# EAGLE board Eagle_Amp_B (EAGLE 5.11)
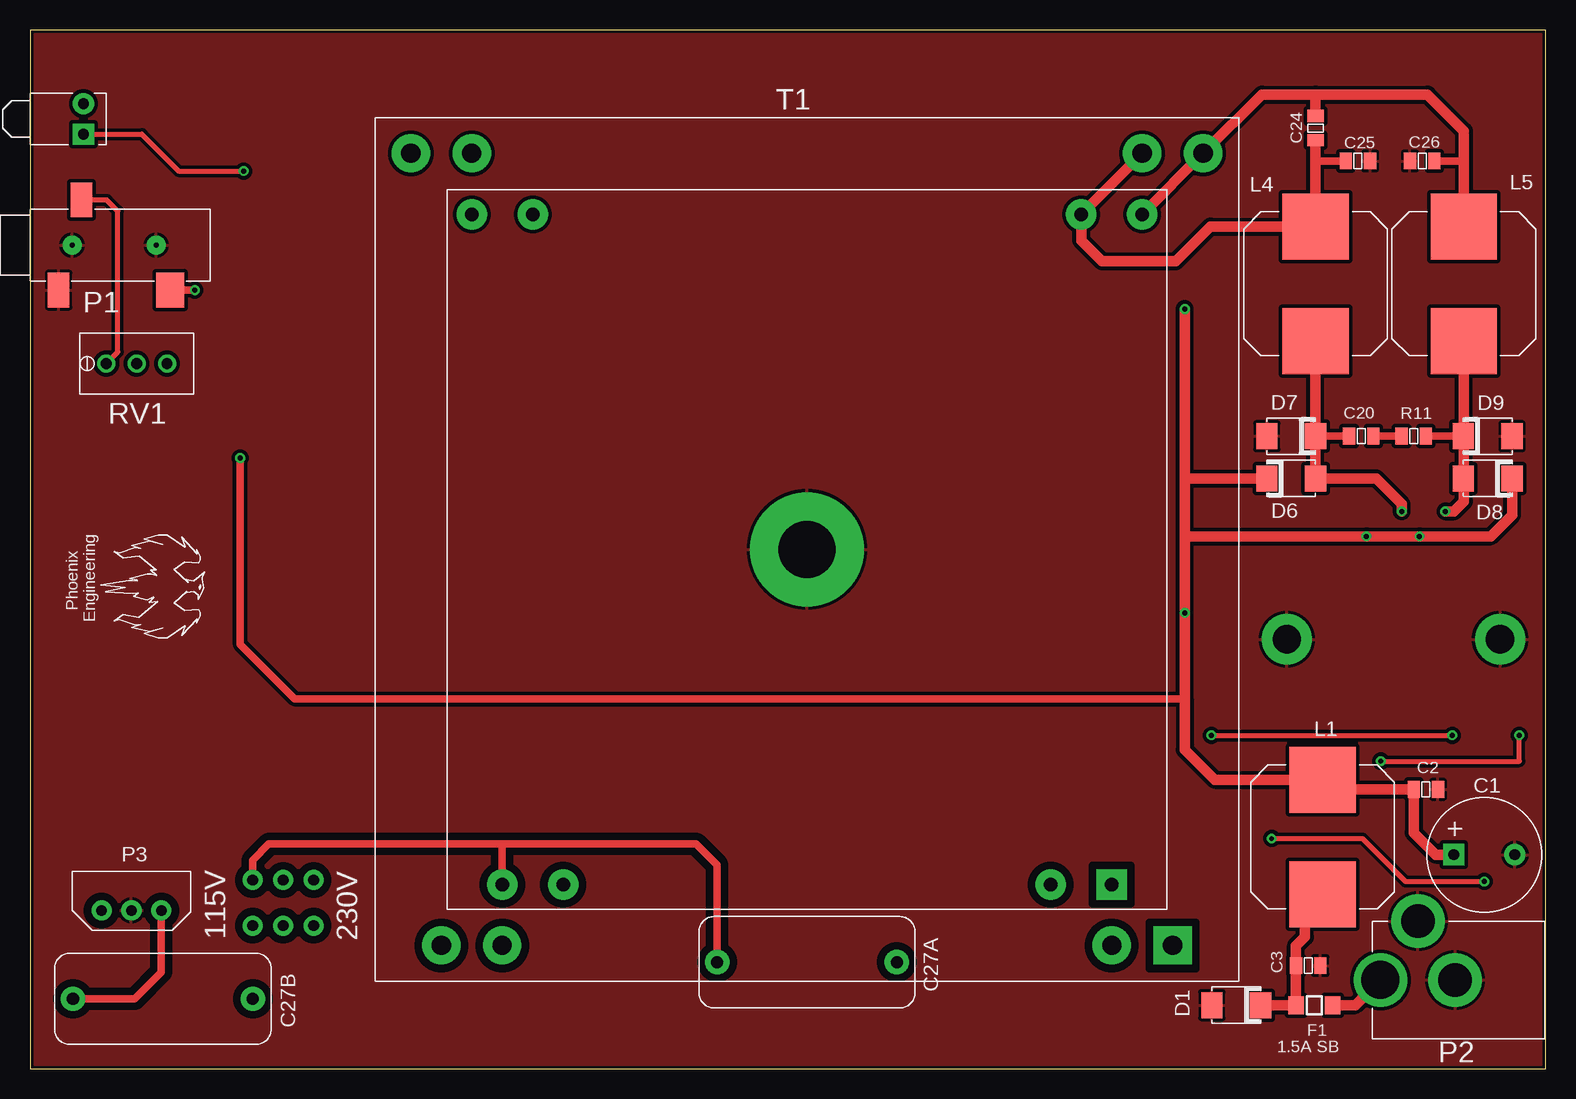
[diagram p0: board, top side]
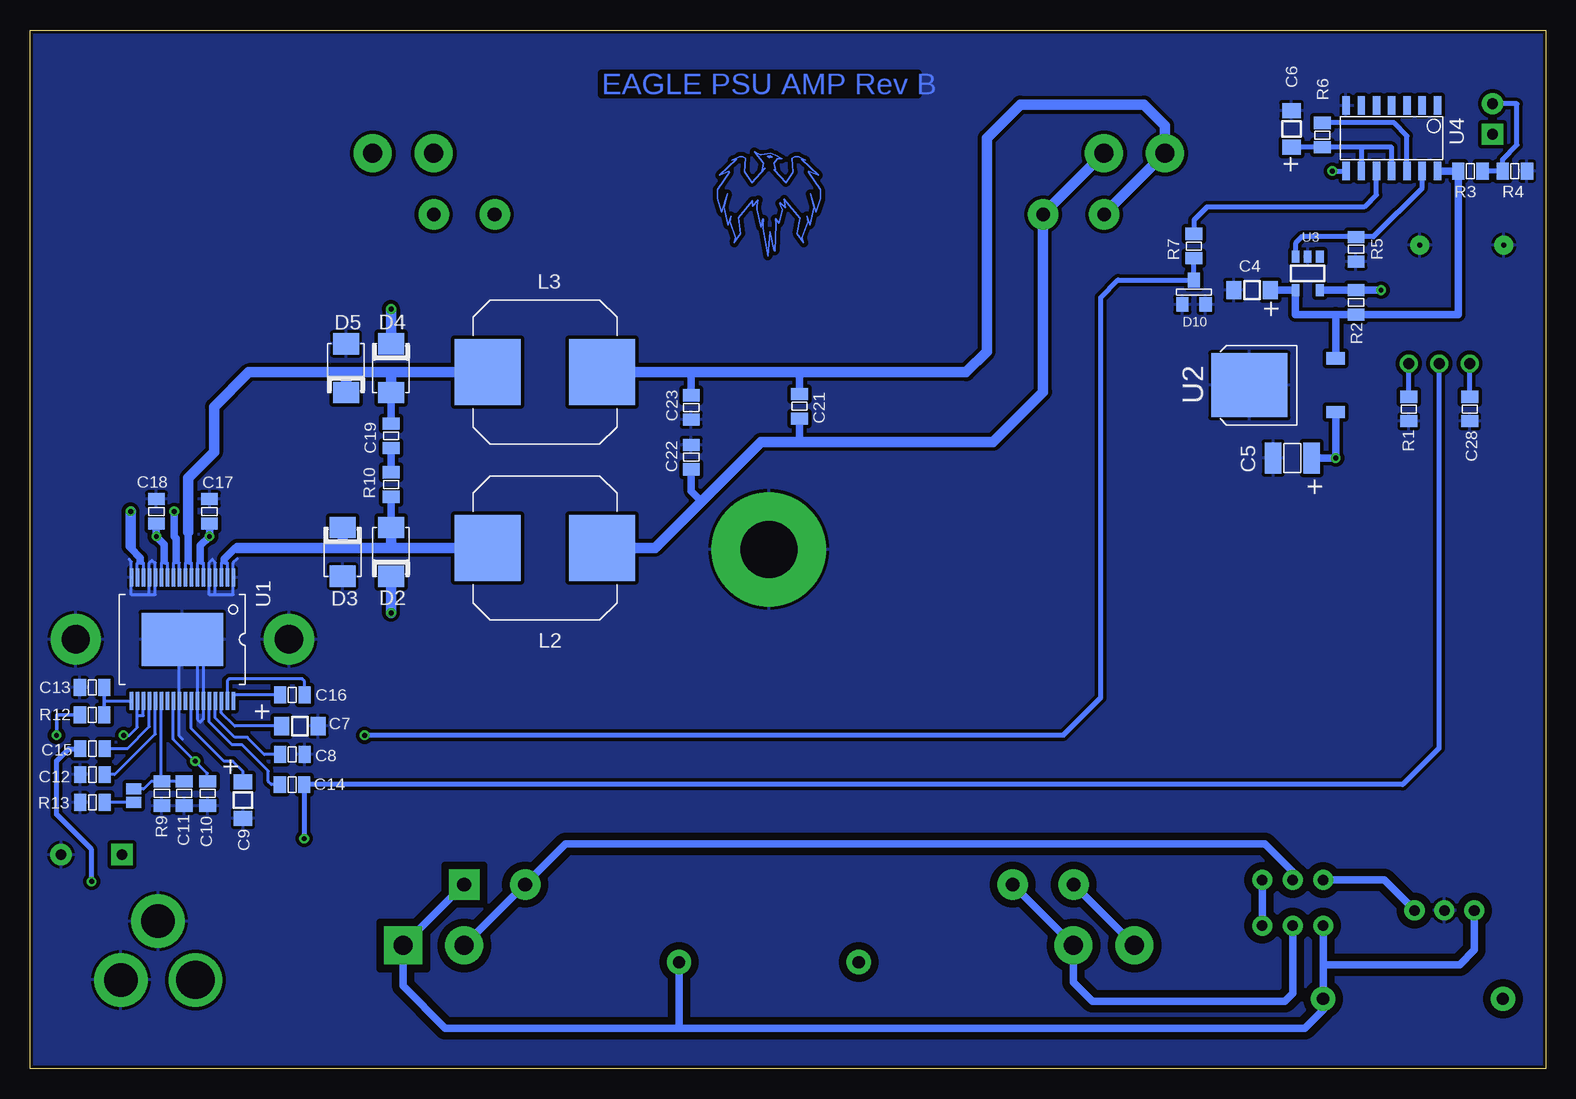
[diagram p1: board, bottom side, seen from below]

Size 126.36 x 86.61 mm. Coordinates in mm from the lower left corner, seen from the top.
Outline: 0,0 126.36,0 126.36,86.61 0,86.61 0,0
Copper layers (1*2+5*16): Top 0.035mm / dielectric 0.5mm / Route2 0.035mm / dielectric 0.5mm / Route5 0.035mm / dielectric 0.5mm / Bottom 0.035mm
Design rules "default": minimum track width 10mil, minimum drill 24mil, track to track 8mil, track to pad 8mil, pad to pad 8mil, via to via 8mil, smd to smd 8mil, copper to edge 0mil, drill to drill 8mil, minimum pad ring 1mil, minimum via ring 1mil, stop-mask expansion 4mil, vias tented up to drill 16mil, thermal gap 10mil
tRestrict: area 88.6,13.8 to 91.8,17; area 37.9,13.9 to 40.8,16.8; area 43,13.9 to 45.9,16.8; area 83.6,13.9 to 86.5,16.8; area 5,12.2 to 7,14.2; area 9.9,12.2 to 12,14.2; area 17.6,10.9 to 19.6,13; area 17.6,14.7 to 19.6,16.8; area 20.1,14.7 to 22.1,16.8; area 22.6,14.7 to 24.7,16.8; area 22.6,10.9 to 24.7,13; area 20.1,10.9 to 22.1,13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; 10 lines
bRestrict: area 83.6,13.9 to 86.5,16.8; area 37.9,13.9 to 40.8,16.8; area 43,13.9 to 45.9,16.8; area 88.6,13.8 to 91.8,17; area 9.9,12.2 to 12,14.2; area 5,12.2 to 7,14.2; area 17.6,14.7 to 19.6,16.8; area 20.1,14.7 to 22.1,16.8; area 22.6,14.7 to 24.7,16.8; area 17.6,10.9 to 19.6,13; area 20.1,10.9 to 22.1,13; area 22.6,10.9 to 24.7,13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; 27 lines

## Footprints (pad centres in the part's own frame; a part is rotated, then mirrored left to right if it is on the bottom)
EL_CAP_10X16 = drill 0.889 pad 1.778 square: P$1 -2.54,0 | drill 0.889 pad 1.778 round: P$2 2.54,0
C0805 = smd 1.016 x 1.397: P$1 -1.016,0; P$2 1.016,0
C1206 = smd 1.524 x 1.27: P$1 0,1.524; P$2 0,-1.524
1210 = smd 1.397 x 2.591: 1 -1.6,0; 2 1.6,0
FILM_224_400V = drill 1.016 pad 2.032 round: P$1 -7.493,0; P$2 7.493,0
SMA = smd 1.778 x 2.159: P$1 2.032,0; P$2 -2.032,0
SOT23 = smd 1.016 x 1.219: 1 -0.94,1.016; 2 0.991,1.016; 3 0.025,-1.016
TP = drill 0.889 pad 1.676 round: P$1 0,0
LED_T1_RA = drill 0.889 pad 1.778 round: P$1 -1.27,0 | drill 0.889 pad 1.778 square: P$2 1.27,0
SMJUMP-S = smd 0.889 x 1.27: P$1 0.559,0; P$2 -0.559,0
TOROID35VA = drill 1.587 pad 3.175 round: P$1 -33.02,-33.02; P$2 -27.94,-33.02; P$3 33.02,-33.02; P$4 27.94,-33.02; P$6 -25.4,33.02; P$7 30.48,33.02; P$8 25.4,33.02 | drill 1.587 pad 3.175 square: P$5 -30.48,33.02 | drill 4.762 pad 9.525 round: P$9 0,0
2_56_MOUNTING = drill 2.362 pad 4.191 round: P$1 0,0
MSS1278 = smd 5.512 x 5.512: P$1 0,4.775; P$2 0,-4.775
3.5MMST_RA_SMT-3 = smd 1.803 x 2.896: P$1 5.131,3.759; P$2 3.226,-3.759 | smd 2.311 x 2.896: P$3 -4.166,3.759 | drill 0.406 pad 1.587 round: P$5 -2.997,0; P$6 4.013,0
2.5MMRA_PWR = drill 2.794 pad 4.445 round: P$1 0,0; P$3 3.099,-4.902 | drill 3.175 pad 4.445 round: P$2 6.223,0
10MM_10T_V = drill 0.889 pad 1.524 round: P$1 -2.54,0; P$2 0,0; P$3 2.54,0
TOROID15VA = drill 1.143 pad 2.54 round: P$1 -27.94,-27.94; P$2 -22.86,-27.94; P$3 27.94,-27.94; P$4 22.86,-27.94; P$6 -20.32,27.94; P$7 25.4,27.94; P$8 20.32,27.94 | drill 1.143 pad 2.54 square: P$5 -25.4,27.94 | drill 4.762 pad 9.525 round: P$9 0,0
SO36_POWER_PAD = smd 0.27 x 1.5: P$1 -4.25,-5.15; P$2 -3.75,-5.15; P$3 -3.25,-5.15; P$4 -2.75,-5.15; P$5 -2.25,-5.15; P$6 -1.75,-5.15; P$7 -1.25,-5.15; P$8 -0.75,-5.15; P$9 -0.25,-5.15; P$10 0.25,-5.15; P$11 0.75,-5.15; P$12 1.25,-5.15; P$13 1.75,-5.15; P$14 2.25,-5.15; P$15 2.75,-5.15; P$16 3.25,-5.15; P$17 3.75,-5.15; P$18 4.25,-5.15; P$19 4.25,5.15; P$20 3.75,5.15; P$21 3.25,5.15; P$22 2.75,5.15; P$23 2.25,5.15; P$24 1.75,5.15; P$25 1.25,5.15; P$26 0.75,5.15; P$27 0.25,5.15; P$28 -0.25,5.15; P$29 -0.75,5.15; P$30 -1.25,5.15; P$31 -1.75,5.15; P$32 -2.25,5.15; P$33 -2.75,5.15; P$34 -3.25,5.15; P$35 -3.75,5.15; P$36 -4.25,5.15 | smd 6.8 x 4.4: P$37 0,0
TO-252 = smd 5.334 x 6.35: P$1 0,0.889 | smd 1.016 x 1.524: P$2 -2.235,-6.299; P$3 2.235,-6.299
SOT23-5 = smd 1.016 x 0.635: 1 -1.397,1.016; 2 -1.397,0; 3 -1.397,-1.016; 4 1.397,-1.016; 5 1.397,1.016
SO-14 = smd 0.61 x 1.524: 1 -3.81,-2.794; 2 -2.54,-2.794; 3 -1.27,-2.794; 4 0,-2.794; 5 1.27,-2.794; 6 2.54,-2.794; 7 3.81,-2.794; 8 3.81,2.667; 9 2.54,2.667; 10 1.27,2.667; 11 0,2.667; 12 -1.27,2.667; 13 -2.54,2.667; 14 -3.81,2.667

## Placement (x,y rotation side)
C1  [EL_CAP_10X16]  121.23,17.86 0 top
C2  [C0805]  116.36,23.29 0 top
C3  [C0805]  106.55,8.61 0 top
C4  [C1206]  24.49,64.92 90 bottom
C5  [1210]  21.13,50.93 0 bottom
C6  [C1206]  21.21,78.36 0 bottom
C7  [C1206]  103.86,28.57 90 bottom
C8  [C0805]  104.5,26.21 0 bottom
C9  [C1206]  108.61,22.4 0 bottom
C10  [C0805]  111.56,22.96 270 bottom
C11  [C0805]  113.51,22.96 270 bottom
C12  [C0805]  121.16,24.54 180 bottom
C13  [C0805]  121.18,31.8 180 bottom
C14  [C0805]  104.52,23.7 0 bottom
C15  [C0805]  121.16,26.7 180 bottom
C16  [C0805]  104.5,31.17 180 bottom
C17  [C0805]  111.4,46.48 90 bottom
C18  [C0805]  115.82,46.48 270 bottom
C19  [C0805]  96.27,52.78 270 bottom
C20  [C0805]  110.97,52.76 0 top
C21  [C0805]  62.23,55.24 90 bottom
C22  [C0805]  71.25,51 270 bottom
C23  [C0805]  71.25,55.14 270 bottom
C24  [C0805]  107.16,78.44 90 top
C25  [C0805]  110.69,75.69 0 top
C26  [C0805]  116.05,75.69 0 top
C27A  [FILM_224_400V]  64.77,8.89 0 top
C27B  [FILM_224_400V]  11.07,5.84 0 top
C28  [C0805]  6.35,55.02 270 bottom
D1  [SMA]  100.56,5.31 0 top
D2  [SMA]  96.27,43.1 90 bottom
D3  [SMA]  100.3,43.1 90 bottom
D4  [SMA]  96.27,58.42 270 bottom
D5  [SMA]  100.03,58.42 270 bottom
D6  [SMA]  105.13,49.23 0 top
D7  [SMA]  105.13,52.76 0 top
D8  [SMA]  121.51,49.23 180 top
D9  [SMA]  121.51,52.76 180 top
D10  [SOT23]  29.31,64.74 180 bottom
E$1  [TP]  8.46,13.21 90 top
E$2  [TP]  5.97,13.21 90 top
E$3  [TP]  10.95,13.21 90 top
E$4  [LED_T1_RA]  4.45,79.2 270 top
E$5  [TP]  21.11,15.75 90 top
E$6  [TP]  18.57,15.75 90 top
E$7  [TP]  23.65,15.75 90 top
E$8  [TP]  21.11,11.94 90 top
E$9  [TP]  18.57,11.94 90 top
E$10  [TP]  23.65,11.94 90 top
E$11  [PHOENIX_LOGO_CU]  64.77,73.3 0 bottom
E$12  [PHOENIX_LOGO]  11.43,40.23 270 top
E$13  [SMJUMP-S]  117.73,22.78 90 bottom
E$14  [TOROID35VA]  64.77,43.31 180 top
E$17  [2_56_MOUNTING]  122.56,35.81 0 top
E$18  [2_56_MOUNTING]  104.78,35.81 0 top
F1  [C1206]  107.06,5.31 90 top
L1  [MSS1278]  107.75,19.33 0 top
L2  [MSS1278]  83.44,43.43 270 bottom
L3  [MSS1278]  83.44,58.09 270 bottom
L4  [MSS1278]  107.16,65.46 0 top
L5  [MSS1278]  119.53,65.46 0 top
P1  [3.5MMST_RA_SMT-3]  7.52,68.68 180 top
P2  [2.5MMRA_PWR]  118.8,7.42 180 top
R1  [C0805]  11.43,55.02 90 bottom
R2  [C0805]  15.82,63.91 270 bottom
R3  [C0805]  6.3,74.85 0 bottom
R4  [C0805]  2.59,74.85 0 bottom
R5  [C0805]  15.82,68.33 90 bottom
R6  [C0805]  18.64,77.85 90 bottom
R7  [C0805]  29.34,68.61 90 bottom
R9  [C0805]  115.37,22.96 90 bottom
R10  [C0805]  96.27,48.72 90 bottom
R11  [C0805]  115.34,52.76 180 top
R12  [C0805]  121.18,29.51 180 bottom
R13  [C0805]  121.16,22.23 0 bottom
RV1  [10MM_10T_V]  8.89,58.8 180 top
T1  [TOROID15VA]  64.77,43.31 180 top
U1  [SO36_POWER_PAD]  113.67,35.81 180 bottom
U2  [TO-252]  23.83,57 90 bottom
U3  [SOT23-5]  19.86,66.32 270 bottom
U4  [SO-14]  12.85,77.52 180 bottom

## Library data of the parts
C1 E$1-E$13 E$17 E$18 P1 P2 RV1 = WJC
C2-C4 C6-C26 C28 D10 F1 R1-R7 R9-R13 U3 = RF
C5 U2 = SMD
C27A C27B E$14 T1 = TUBEAMPS
D1-D9 = SMD-SPC
L1-L5 = COILCRAFT
U1 U4 = SMD-IC

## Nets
$GND: C1.P$2 C2.P$2 C3.P$2 C4.P$1 C5.1 C6.P$1 C7.P$2 C8.P$2 C9.P$2 C10.P$2 C11.P$2 C12.P$2 C13.P$2 C17.P$2 C18.P$1 C22.P$1 C23.P$2 C25.P$2 C26.P$1 C28.P$2 D1.P$2 D3.P$2 D5.P$2 D7.P$2 D9.P$2 D10.1 D10.2 E$1.P$1 E$14.P$9 E$17.P$1 E$18.P$1 P1.P$1 P1.P$5 P1.P$6 P2.P$1 P2.P$3 R1.P$1 R4.P$2 R5.P$1 R9.P$1 R13.P$1 T1.P$9 U1.P$1 U1.P$4 U1.P$5 U1.P$14 U1.P$15 U1.P$18 U1.P$27 U1.P$30 U1.P$31 U1.P$37 U2.P$1 U3.2 U4.7
S$1: F1.P$2 P2.P$2
S$2: C3.P$1 D1.P$1 F1.P$1 L1.P$2
S$3: C19.P$2 R10.P$2
S$4: R5.P$2 U3.3 U4.13
S$5: D2.P$1 D3.P$1 L2.P$2 R10.P$1 U1.P$2 U1.P$3
S$6: R1.P$2 RV1.P$1
S$7: C19.P$1 D4.P$1 D5.P$1 L3.P$2 U1.P$8 U1.P$9
S$8: C20.P$2 R11.P$2
S$9: C13.P$1 R12.P$1 U1.P$19
S$10: E$4.P$2 U4.8
S$11: C24.P$1 C25.P$1 E$14.P$2 L4.P$1 T1.P$2
S$12: C10.P$1 R12.P$2 U1.P$26
S$13: C21.P$2 C23.P$1 E$14.P$3 L3.P$1 T1.P$3
S$15: E$5.P$1 E$14.P$6 T1.P$6
S$16: C28.P$1 P1.P$2 RV1.P$3
S$17: C4.P$2 R2.P$2 R3.P$1 U2.P$3 U3.4 U4.14
S$18: P1.P$3 R2.P$1 U3.5
S$19: D8.P$1 D9.P$1 L5.P$2 R11.P$1 U1.P$16 U1.P$17
S$20: E$13.P$2 R13.P$2
S$21: C24.P$2 C26.P$2 E$14.P$1 L5.P$1 T1.P$1
S$22: C27A.P$1 C27B.P$1 E$3.P$1 E$6.P$1 E$14.P$7 T1.P$7
S$23: C1.P$1 C2.P$1 C5.2 C17.P$1 C18.P$2 D2.P$2 D4.P$2 D6.P$2 D8.P$2 L1.P$1 U1.P$6 U1.P$7 U1.P$12 U1.P$13 U2.P$2
S$24: R6.P$2 U4.12
S$25: C6.P$2 R6.P$1 U4.9 U4.11
S$26: R7.P$2 U4.10
S$27: E$8.P$1 E$14.P$8 T1.P$8
S$29: E$4.P$1 R3.P$2 R4.P$1
S$31: C20.P$1 D6.P$1 D7.P$1 L4.P$2 U1.P$10 U1.P$11
S$33: E$7.P$1 E$10.P$1
S$34: C27A.P$2 C27B.P$2 E$2.P$1 E$9.P$1 E$14.P$5 T1.P$5
S$35: C21.P$1 C22.P$2 E$14.P$4 L2.P$1 T1.P$4
S$38: C16.P$2 U1.P$36
S$39: C16.P$1 U1.P$35
S$40: C9.P$1 U1.P$29
S$41: C7.P$1 U1.P$34
S$42: D10.3 R7.P$1 U1.P$20 U1.P$21
S$43: C12.P$1 U1.P$23
S$44: C15.P$1 U1.P$22
S$45: C8.P$1 U1.P$33
S$46: C14.P$1 U1.P$32
S$47: C11.P$1 E$13.P$1 R9.P$2 U1.P$24
S$49: C14.P$2 C15.P$2 RV1.P$2

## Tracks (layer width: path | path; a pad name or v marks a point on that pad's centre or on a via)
$GND
  Bottom 0.254: 113.67,27.51 113.92,27.76 U1.P$27 113.92,35.56 U1.P$37 | U1.P$37 111.92,35.81 U1.P$31 111.92,29.16 112.17,28.91 112.42,29.15 U1.P$30 112.42,35.81 U1.P$37 | 110.92,39.52 U1.P$4 110.92,42.21 111.18,42.47 111.42,42.23 U1.P$5 111.42,39.52 110.92,39.52 | 109.09,42.52 109.42,42.2 U1.P$1 109.42,39.52 110.92,39.52 | 118.14,42.49 117.92,42.27 U1.P$18 117.92,39.52 116.42,39.52 | 116.42,39.52 U1.P$15 116.42,42.18 116.18,42.39 115.92,42.18 U1.P$14 115.92,39.52 116.42,39.52
  pour Top (isolate 0.305): 0.38,0.38 125.98,0.38 125.98,86.23 0.38,86.23
  pour Bottom (isolate 0.305): 0.38,0.38 125.98,0.38 125.98,86.23 0.38,86.23
S$1
  Top 0.889: F1.P$2 110.47,5.31 P2.P$2
S$2
  Top 0.889: D1.P$1 F1.P$1 C3.P$1 105.54,10.26 106.27,11 106.27,13.08 L1.P$2
S$3
  Bottom 0.635: R10.P$2 C19.P$2
S$4
  Bottom 0.406: U3.3 20.88,68.83 20.34,69.37 16.36,69.37 | 16.36,69.37 R5.P$2 | 16.36,69.37 14.38,69.37 10.31,73.43 U4.13
S$5
  Bottom 0.254: U1.P$2 109.92,42.19 110.16,42.19 | U1.P$3 110.42,42.19 110.16,42.19 | 110.16,42.39 110.16,42.19
  Bottom 0.635: 109.07,43.43 109.25,43.43 110.16,42.52 110.16,42.39 | D2.P$1 R10.P$1
  Bottom 0.889: L2.P$2 96.27,43.43 | 96.27,43.43 100.31,43.43 | 100.31,43.43 109.07,43.43 | 100.31,43.43 D3.P$1 | 96.27,43.43 D2.P$1
S$6
  Bottom 0.406: R1.P$2 RV1.P$1
S$7
  Bottom 0.254: U1.P$8 112.92,42.19 113.16,42.19 | U1.P$9 113.42,42.19 113.16,42.19 | 113.16,42.39 113.16,42.19
  Bottom 0.635: 113.16,44.78 113.16,42.39 | D4.P$1 C19.P$1
  Bottom 0.889: L3.P$2 96.27,58.09 | 96.27,58.09 100.03,58.09 | 100.03,58.09 108.13,58.09 111.02,55.19 111.02,51.41 113.16,49.28 113.16,44.78 | 100.03,58.09 D5.P$1 | 96.27,58.09 D4.P$1
S$8
  Top 0.635: C20.P$2 R11.P$2
S$9
  Bottom 0.254: C13.P$1 120.17,31.56 | U1.P$19 120.17,30.66 120.17,30.86
  Bottom 0.305: R12.P$1 120.17,30.86 C13.P$1
S$10  (via drill 0.41 pad 0.81)
  Top 0.406: v17.8,74.85 12.39,74.85 9.32,77.93 E$4.P$2
  Bottom 0.406: v17.8,74.85 U4.8
S$11
  Top 0.635: 107.16,75.69 C25.P$1
  Top 0.889: C24.P$1 107.16,75.69 L4.P$1 98.4,70.23 95.5,67.33 89.36,67.33 87.63,69.06 T1.P$2 E$14.P$2
S$12  (via drill 0.41 pad 0.81)
  Top 0.406: v112.6,25.65 124.16,25.65 v124.16,27.81
  Bottom 0.254: 114.42,27.48 U1.P$26 | 114.42,27.48 114.4,27.48 | 114.42,27.48 114.42,27.47 v112.6,25.65 111.58,24.64 111.58,23.98 C10.P$1
  Bottom 0.305: v124.16,27.81 124.16,29.52 R12.P$2
S$13
  Bottom 0.635: 71.25,58.09 C23.P$1 | 62.23,58.09 C21.P$2
  Bottom 0.889: L3.P$1 71.25,58.09 62.23,58.09 48.34,58.09 46.61,59.82 46.61,77.6 43.81,80.39 33.5,80.39 31.75,78.64 E$14.P$3 T1.P$3
S$15
  Bottom 0.635: E$5.P$1 21.11,16.43 23.42,18.75 81.71,18.75 T1.P$6 E$14.P$6
S$16
  Top 0.406: P1.P$2 6.4,72.44 7.32,71.53 7.32,59.77 RV1.P$3
  Bottom 0.406: C28.P$1 RV1.P$3
S$17
  Bottom 0.61: C4.P$2 U3.4 20.88,62.89 17.53,62.89 R2.P$2 7.32,62.89 R3.P$1 U4.14
  Bottom 0.635: 17.53,62.89 U2.P$3
S$18  (via drill 0.41 pad 0.81)
  Top 0.61: P1.P$3 v13.74,64.92
  Bottom 0.61: v13.74,64.92 R2.P$1 U3.5
S$19  (via drill 0.41 pad 0.81)
  Top 0.635: D9.P$1 R11.P$1
  Top 0.889: v117.98,46.48 118.69,46.48 119.53,47.32 119.53,49.23 | 119.53,49.23 119.53,52.76 | 119.53,52.76 L5.P$2 | 119.53,52.76 D9.P$1 | 119.53,49.23 D8.P$1
  Bottom 0.254: U1.P$17 117.42,42.19 117.17,42.19 | U1.P$16 116.92,42.19 117.17,42.19 | 117.17,42.19 117.17,42.39
  Bottom 0.635: 117.98,43.59 117.98,43.41 117.17,42.6 117.17,42.39
  Bottom 0.889: 117.98,43.59 v117.98,46.48
S$20
  Bottom 0.254: E$13.P$2 R13.P$2
S$21
  Top 0.635: 119.53,75.69 C26.P$2 | 119.51,77.85 119.53,77.83 119.53,78.18
  Top 0.889: L5.P$1 119.53,75.69 119.53,77.83 | 119.53,78.18 116.48,81.23 107.16,81.23 | 107.16,81.23 C24.P$2 | T1.P$1 E$14.P$1 102.69,81.23 107.16,81.23
S$22
  Top 0.635: E$6.P$1 18.57,17.4 19.91,18.75 39.37,18.75 | 39.37,18.75 T1.P$7 | C27B.P$1 8.74,5.84 10.95,8.05 E$3.P$1 | C27A.P$1 57.28,16.99 55.52,18.75 39.37,18.75
  Bottom 0.635: T1.P$7 E$14.P$7 | E$3.P$1 13.49,15.75 E$6.P$1
S$23  (via drill 0.41 pad 0.81)
  Top 0.635: 96.27,30.86 22.05,30.86 17.53,35.38 v17.53,50.93
  Top 0.889: D8.P$2 123.55,46.18 121.77,44.4 v115.82,44.4 v111.4,44.4 96.27,44.4 | 96.27,49.23 v96.27,63.35 | 96.27,49.23 D6.P$2 | 96.27,44.4 96.27,49.23 | 96.27,44.4 v96.27,38.02 96.27,30.86 96.27,26.59 98.75,24.11 L1.P$1 108.56,23.29 C2.P$1 115.34,19.68 117.17,17.86 C1.P$1
  Bottom 0.254: U1.P$13 115.42,42.19 115.16,42.19 | U1.P$12 114.92,42.19 115.16,42.19 | U1.P$7 112.42,42.19 112.17,42.19 | U1.P$6 111.92,42.19 112.17,42.19 | 115.16,42.39 115.16,42.19 | 112.17,42.39 112.17,42.19
  Bottom 0.61: U2.P$2 v17.53,50.93 C5.2
  Bottom 0.635: 115.16,42.39 115.16,43.74 v115.82,44.4 C18.P$2 | 112.17,42.39 112.17,43.64 v111.4,44.4 C17.P$1
  Bottom 0.889: v96.27,63.35 D4.P$2 | v96.27,38.02 D2.P$2
S$24
  Bottom 0.406: R6.P$2 12.65,78.87 11.58,77.8 U4.12
S$25
  Bottom 0.406: C6.P$2 R6.P$1 15.39,76.83 | 15.39,76.83 U4.9 | U4.11 12.85,76.83 15.39,76.83
S$26
  Bottom 0.406: R7.P$2 29.34,70.76 28.25,71.86 15.14,71.86 14.12,72.87 U4.10
S$27
  Bottom 0.635: E$8.P$1 21.11,6.3 21.77,5.64 37.8,5.64 39.37,7.21 E$14.P$8 T1.P$8
S$29
  Bottom 0.406: R3.P$2 R4.P$1 3.61,75.82 2.41,77.01 2.41,80.47 E$4.P$1
S$31  (via drill 0.41 pad 0.81)
  Top 0.635: D7.P$1 C20.P$1
  Top 0.889: L4.P$2 D7.P$1 D6.P$1 112.22,49.23 114.35,47.09 v114.35,46.48
  Bottom 0.254: U1.P$10 113.92,42.19 114.17,42.19 | U1.P$11 114.42,42.19 114.17,42.19 | 114.17,42.19 114.17,42.39
  Bottom 0.635: v114.35,46.48 114.35,44.4 114.17,44.22 114.17,42.39
S$33
  Bottom 0.635: E$10.P$1 E$7.P$1
S$34
  Bottom 0.635: 72.26,3.4 20.09,3.4 18.57,4.93 C27B.P$2 E$9.P$1 18.57,8.79 18.47,8.69 7.19,8.69 5.97,9.91 E$2.P$1 | 72.26,3.4 91.75,3.4 95.25,6.91 E$14.P$5 T1.P$5 | 72.26,3.4 C27A.P$2
S$35
  Bottom 0.635: 70.4,47.31 71.25,48.16 C22.P$2 | 62.23,52.27 C21.P$1
  Bottom 0.889: L2.P$1 74.27,43.43 70.4,47.31 65.43,52.27 62.23,52.27 46.08,52.27 41.91,56.44 T1.P$4 E$14.P$4
S$38
  Bottom 0.254: C16.P$2 109.41,31.17 U1.P$36
S$39
  Bottom 0.254: U1.P$35 109.92,32.38 109.78,32.51 103.66,32.51 103.48,32.33 C16.P$1
S$40
  Bottom 0.254: U1.P$29 112.92,28.38 110.19,25.65 109.45,25.65 108.61,24.82 C9.P$1
S$41
  Bottom 0.254: C7.P$1 109.3,28.57 110.42,29.69 U1.P$34
S$42  (via drill 0.41 pad 0.81)
  Top 0.406: v98.48,27.81 v118.57,27.81
  Bottom 0.254: 117.42,29.46 U1.P$20 | U1.P$21 116.92,29.46 117.42,29.46 | 117.42,29.46 117.42,28.48 118.08,27.81 v118.57,27.81
  Bottom 0.406: v98.48,27.81 40.26,27.81 37.11,30.96 37.11,64.31 35.66,65.76 D10.3 R7.P$1
S$43
  Bottom 0.254: C12.P$1 119.3,24.54 115.92,27.93 U1.P$23
S$44
  Bottom 0.254: C15.P$1 118.26,26.7 116.42,28.54 U1.P$22
S$45
  Bottom 0.254: U1.P$33 110.92,29.25 109.3,27.64 108.25,27.64 106.83,26.21 C8.P$1
S$46
  Bottom 0.254: U1.P$32 111.42,28.92 109.53,27.03 108.69,27.03 106.5,24.84 106.5,23.98 106.22,23.7 C14.P$1
S$47
  Bottom 0.254: C11.P$1 R9.P$2 | U1.P$24 115.42,23.98 R9.P$2 | R9.P$2 116.26,23.98 116.89,23.34 E$13.P$1
S$49  (via drill 0.41 pad 0.81)
  Top 0.406: v103.5,19.2 111.07,19.2 114.66,15.62 v121.23,15.62
  Bottom 0.406: C15.P$2 123.14,26.7 124.16,25.68 124.16,21.21 121.23,18.29 v121.23,15.62 | v103.5,19.2 C14.P$2 11.94,23.7 8.89,26.75 RV1.P$2

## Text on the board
Bottom: EAGLE PSU AMP Rev B
tPlace: Engineering | Phoenix | + | P3 | 115V | 230V | 1.5A SB
bPlace: + | + | + | + | +
bStop: EAGLE PSU AMP Rev B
